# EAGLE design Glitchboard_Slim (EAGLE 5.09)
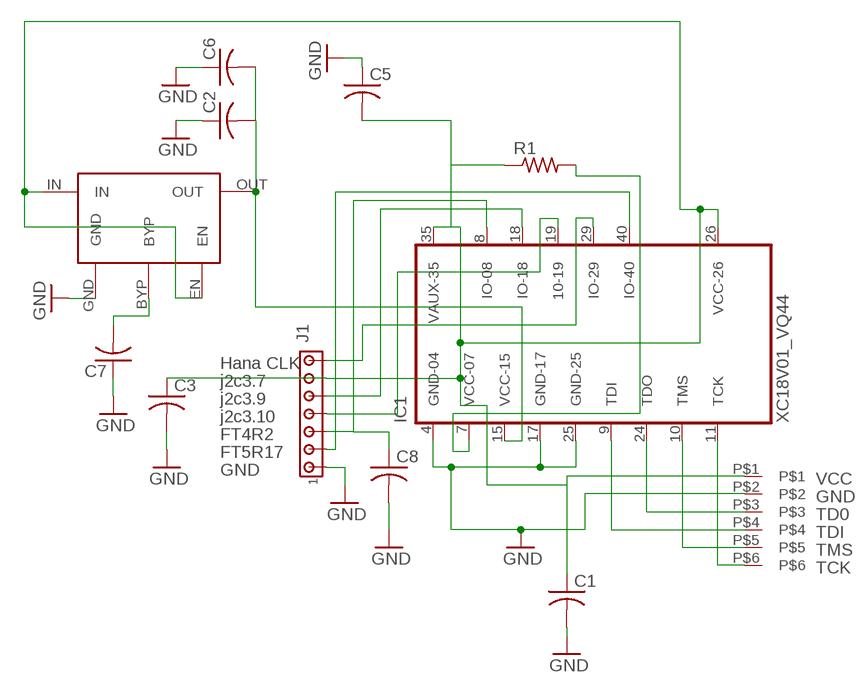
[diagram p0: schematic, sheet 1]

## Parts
C1  C-USC0805  [C0805]
C2  C-USC0805  [C0805]
C3  C-USC0805  [C0805]
C5  C-USC0805  [C0805]
C6  C-USC0805  [C0805]
C7  C-USC0805  [C0805]
C8  C-USC0805  [C0805]
IC1  XC18V01_VQ44  [SQFP-S-10X10-44]
J1  MTA07-100  [10X07MTA]
R1  R-US_R1206  [R1206]
U$5  6PINHEADERNEW  [6PINHEADERNEW]
VREG1  VREG  [SOT23-5]

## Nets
GND: C1.2 C2.1 C3.2 C5.1 C6.1 C7.1 C8.2 IC1.4(GND-04) IC1.17(GND-17) IC1.25(GND-25) J1.1 U$5.P$2 VREG1.GND
N$1: C1.1 C3.1 C5.2 IC1.26(VCC-26) IC1.35(VAUX-35) J1.6 R1.1 U$5.P$1 VREG1.EN VREG1.IN
N$3: C7.2 VREG1.BYP
N$4: IC1.7(VCC-07) R1.2
N$6: C2.2 C6.2 IC1.15(VCC-15) VREG1.OUT
N$10: IC1.10(TMS) U$5.P$5
N$12: IC1.24(TDO) U$5.P$3
N$17: IC1.9(TDI) U$5.P$4
N$19: IC1.11(TCK) U$5.P$6
N$22: IC1.29(IO-29) J1.7
N$23: IC1.18(IO-18) J1.5
N$24: IC1.19(10-19) J1.4
N$25: C8.1 IC1.8(IO-08) J1.3
N$26: IC1.40(IO-40) J1.2

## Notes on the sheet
- Hana CLK
- j2c3.7
- j2c3.9
- j2c3.10
- FT4R2
- FT5R17
- GND
- VCC
- GND
- TD0
- TDI
- TMS
- TCK

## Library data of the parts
C1-C3 C5-C8 = rcl:C-US: CAPACITOR, American symbol
IC1 = xilinx-xc18v:XC18V01_VQ44: xc18v01_vq44 edit this description Auto generated by make-symbol-device-package-bsdl.ulp Rev. 26 Source: xc18v01_vq44.bsd
J1 = con-amp:MTA07-100: AMP connector
R1 = rcl:R-US_: RESISTOR, American symbol
U$5 = 1_Brian:6PINHEADERNEW
VREG1 = dp_devices:VREG

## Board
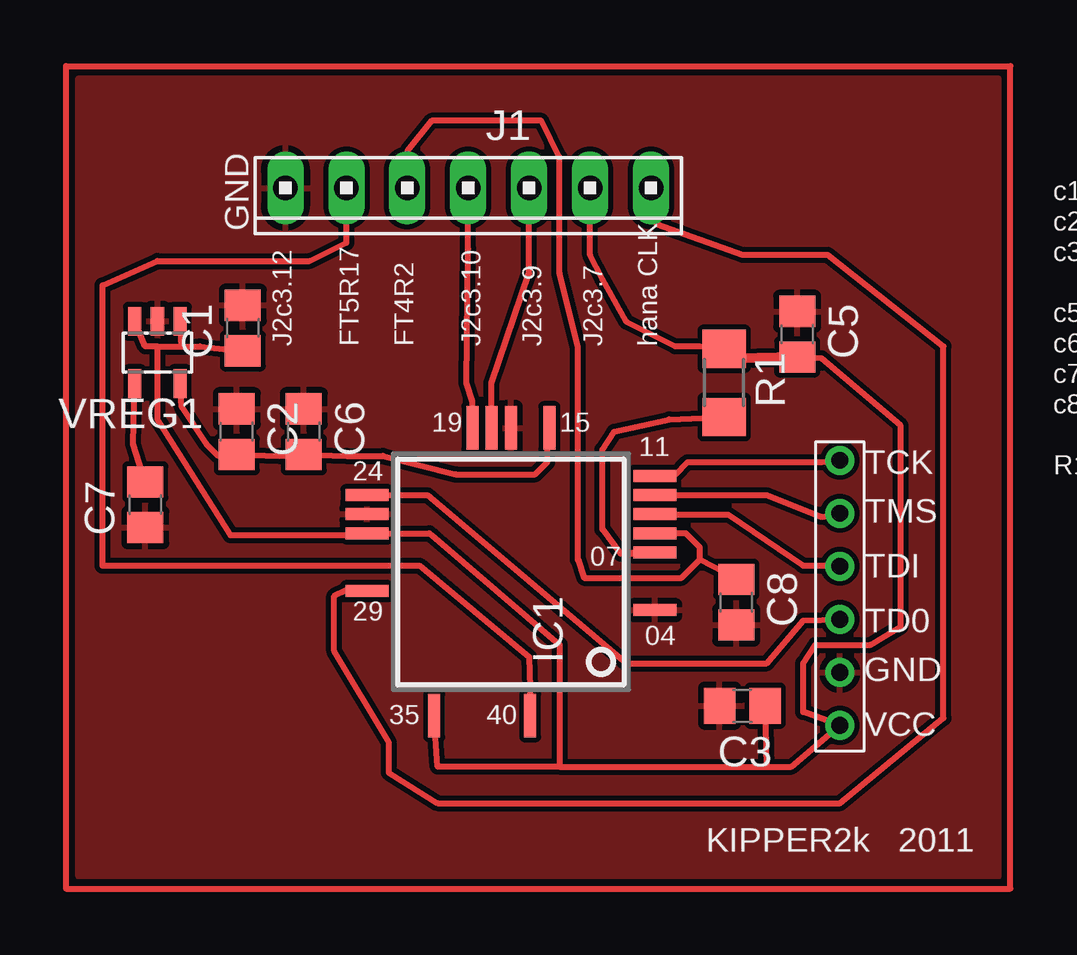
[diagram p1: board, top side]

No outline drawn. Coordinates in mm, seen from the top.
Copper layers (1*16): Top 0.035mm / dielectric 1.5mm / Bottom 0.035mm
Design rules "default": minimum track width 10mil, minimum drill 24mil, track to track 8mil, track to pad 8mil, pad to pad 8mil, via to via 8mil, smd to smd 8mil, copper to edge 40mil, drill to drill 8mil, minimum pad ring 10mil, minimum via ring 8mil, stop-mask expansion 4mil, vias tented up to drill 0mil, thermal gap 10mil

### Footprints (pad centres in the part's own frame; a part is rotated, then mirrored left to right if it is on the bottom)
C0805 = smd 1.3 x 1.5: 1 -0.95,0; 2 0.95,0
SQFP-S-10X10-44 = smd 0.5 x 1.8: 4 -1.6,-6; 7 0.8,-6; 8 1.6,-6; 9 2.4,-6; 10 3.2,-6; 11 4,-6; 24 3.2,6; 25 2.4,6; 26 1.6,6; 29 -0.8,6 | smd 1.8 x 0.5: 15 6,-1.6; 17 6,0; 18 6,0.8; 19 6,1.6; 35 -6,3.2; 40 -6,-0.8
10X07MTA = drill 1.016 long: 1 7.62,0; 2 5.08,0; 3 2.54,0; 4 0,0; 5 -2.54,0; 6 -5.08,0; 7 -7.62,0
R1206 = smd 1.6 x 1.803: 1 -1.422,0; 2 1.422,0
6PINHEADERNEW = drill 0.7 round: P$1 -1.524,6.655; P$2 -1.524,4.445; P$3 -1.524,2.235; P$4 -1.524,0.025; P$5 -1.524,-2.184; P$6 -1.524,-4.394
SOT23-5 = smd 0.55 x 1.2: BYP 0.95,1.3; EN 0.95,-1.3; GND 0,-1.3; IN -0.95,-1.3; OUT -0.95,1.3

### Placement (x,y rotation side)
C1  7.37,23.37 90 top
C2  7.11,19.05 270 top
C3  28.19,7.62 180 top
C5  30.48,23.11 270 top
C6  9.91,19.05 270 top
C7  3.3,16 90 top
C8  27.94,11.94 270 top
IC1  18.54,13.21 90 top
J1  16.76,29.21 180 top
R1  27.43,21.08 270 top
U$5  30.73,13.46 180 top
VREG1  3.81,22.35 180 top

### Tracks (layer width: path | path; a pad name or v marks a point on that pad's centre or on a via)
GND
  pour Top: 0.51,0.51 0.51,33.78 38.86,33.78 38.86,0.51
N$1
  Top 0.254: 20.57,5.08 29.21,5.08 | 29.21,5.08 30.23,5.08 U$5.P$1 30.73,7.37 30.73,9.4 31.24,10.16 33.53,10.16 34.8,10.92 34.8,19.3 31.5,22.1 C5.2 | 20.57,5.08 20.57,10.16 15.24,14.73 15.14,14.81 IC1.26 11.94,14.73 6.86,14.73 3.81,19.56 3.81,22.61 | 29.21,5.08 C3.1 | 20.57,5.08 15.49,5.08 IC1.35 | J1.6 21.84,26.42 22.35,25.4 23.37,23.62 25.4,22.61 26.42,22.61 R1.1 | VREG1.EN 3.3,22.61 3.81,22.61 | 3.81,22.61 4.83,22.61 | 4.83,22.61 VREG1.IN | C1.1 5.59,22.61 4.83,22.61
  Top 0.406: R1.1 27.94,22.1 C5.2
N$3
  Top 0.254: C7.2 2.79,18.54 VREG1.BYP
N$4
  Top 0.254: IC1.7 23.62,14.01 23.62,13.97 23.11,13.97 22.35,14.99 22.35,18.29 22.86,19.05 25.15,19.56 R1.2
N$6
  Top 0.254: VREG1.OUT 4.83,20.07 5.84,18.54 6.35,18.03 C2.2 8.89,18.03 C6.2 11.68,18.03 13.21,18.03 16.26,17.27 19.56,17.27 20.07,17.78 20.07,19.21 IC1.15
N$10
  Top 0.254: IC1.10 25.15,16.41 29.21,16.41 31.5,15.49 U$5.P$5
N$12
  Top 0.254: U$5.P$3 30.73,11.18 29.21,9.4 23.37,9.4 15.06,16.41 14.76,16.41 IC1.24
N$17
  Top 0.254: U$5.P$4 31.75,13.46 30.73,13.46 27.61,15.6 25.32,15.6 IC1.9
N$19
  Top 0.254: IC1.11 25.4,17.27 25.91,17.78 31.5,17.78 U$5.P$6
N$21
  Top 0.254: 39.37,0 39.37,34.29 0,34.29 0,0 39.37,0
N$22
  Top 0.254: J1.7 24.64,27.69 28.19,26.42 31.75,26.42 36.58,22.61 36.58,7.11 32.26,3.56 15.49,3.56 13.46,4.83 13.46,6.1 11.18,9.91 11.18,12.19 11.68,12.45 IC1.29
N$23
  Top 0.254: IC1.18 17.73,19.81 17.73,21.08 19.3,25.65 J1.5
N$24
  Top 0.254: IC1.19 16.94,20.3 16.69,21.08 16.76,26.67 J1.4
N$25
  Top 0.254: IC1.8 25.83,14.81 26.42,14.22 26.42,13.72 | 26.42,13.72 25.65,12.95 21.59,12.95 21.34,13.72 21.34,22.61 20.57,25.65 20.57,30.48 19.81,32 15.24,32 14.22,30.73 J1.3 | C8.1 27.43,12.95 27.43,13.21 26.42,13.72
N$26
  Top 0.254: IC1.40 19.33,8.36 19.3,9.65 14.73,13.46 1.52,13.46 1.52,25.15 3.81,26.16 10.16,26.16 11.68,26.92 J1.2

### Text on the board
tPlace: GND
tNames: c1 = 1uf | c2 = 1uF | c3 =0.047uf | c5 = 0.047uf | J2c3.12 | FT5R17 | FT4R2 | J2c3.10 | J2c3.9 | J2c3.7 | hana CLK | c6 = 0.047uf | c7 = 470pf | c8 = 220pf | 19 | 15 | 11 | 24 | TCK | R1 = leave off | TMS | 07 | TDI | 29 | TD0 | 04 | GND | 35 | 40 | VCC | KIPPER2k 2011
